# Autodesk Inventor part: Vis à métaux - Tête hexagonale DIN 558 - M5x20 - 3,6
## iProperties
Created: 2002-06
Part Number: Vis à métaux - Tête hexagonale DIN 558 - M5x20 - 3,6
Material: Par défaut
Catalog Web Link: www.traceparts.com
Description: Vis à métaux - Tête hexagonale DIN 558 - M5x20 - 3,6
Document SubType Name: Modélisation
Designer: Maison
Control State: 0
Master: False
Checked Out: False
Shininess: 20.0
Length Units: 11269
Angle Units: 11279
Time Units: 11290
Mass Units: 11283
Length Display Precision: 3
Angle Display Precision: 2
Density: 0.0
Volumn: 0.0
Area: 0.0
PropertySet Name: Model Information
Author: Maison
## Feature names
1. Base1
